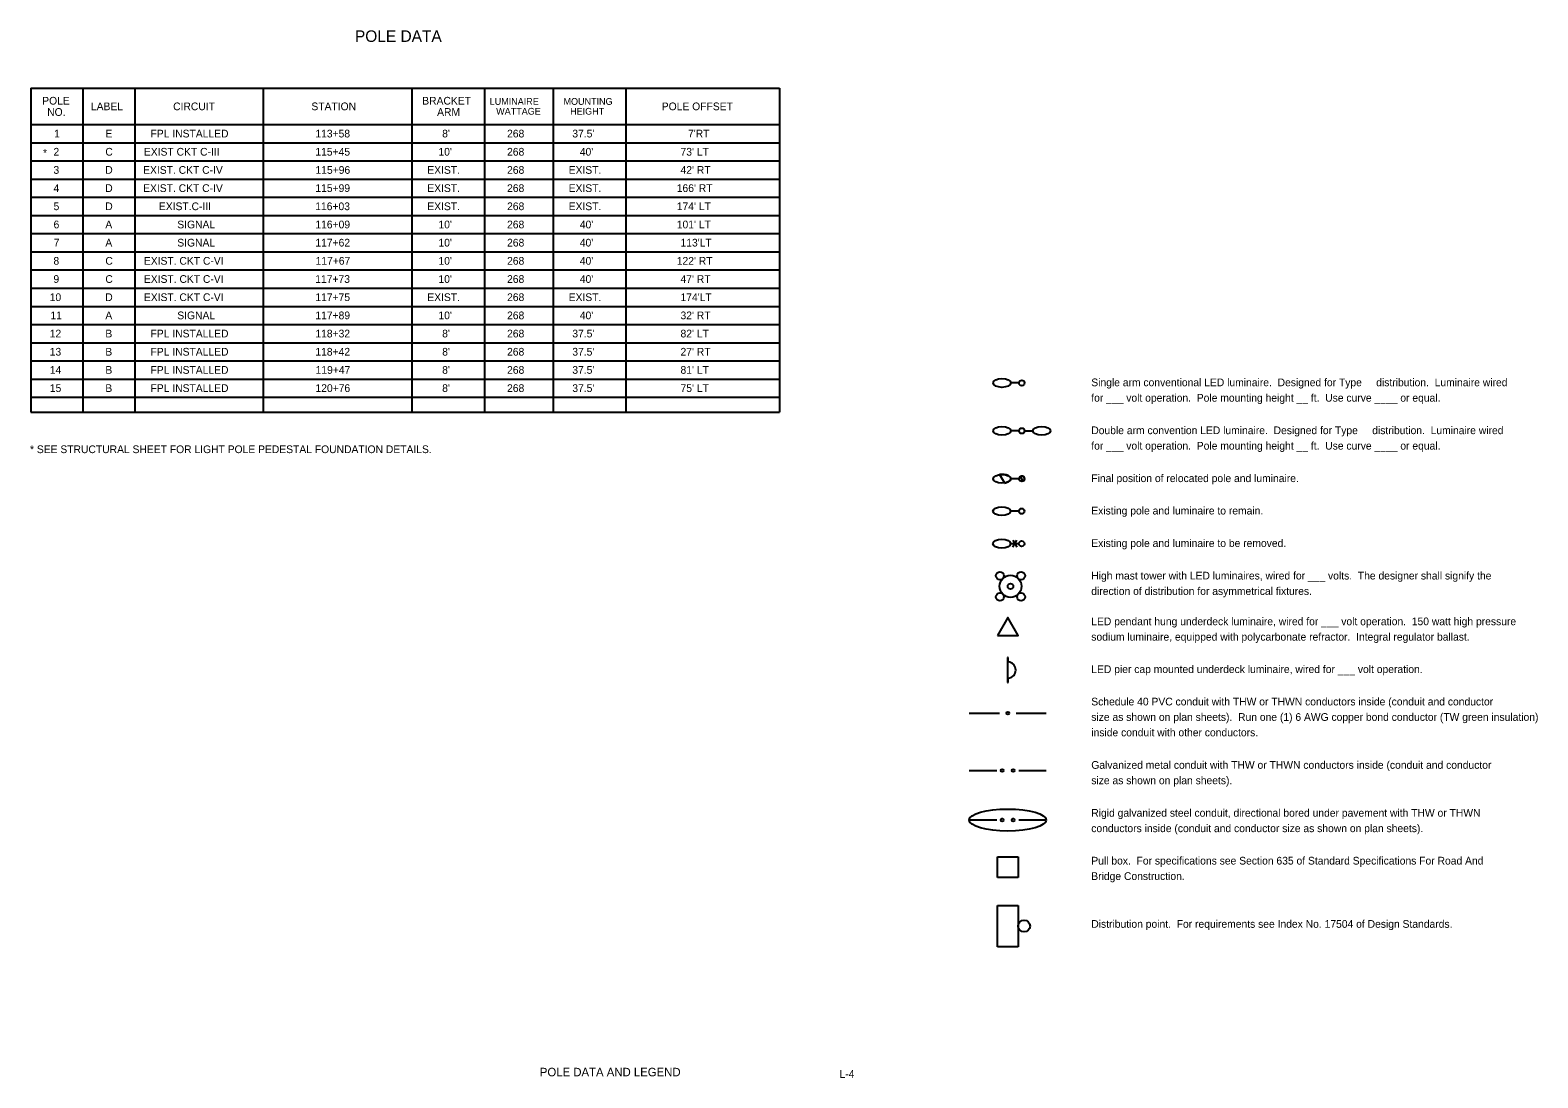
# Model space of a CAD drawing. Extents: x 0.1 to 21.4, y -0.2 to 9.3.
# Drawn here: x 7.72 to 21.4, y -0.21 to 9.3 of the extents above; entities that cross this region are included whole.
import ezdxf

# ---------------------------------------------------------------- set-up
doc = ezdxf.new("R2010")
doc.units = 0
for name, color, linetype in [('NonPlottingEle_dp', 7, 'Continuous'), ('SumBoxBorder_dp', 7, 'Continuous'), ('SumBoxLines_dp', 7, 'Continuous'), ('SumBoxLinesMin_dp', 7, 'Continuous'), ('TextLabel', 7, 'Continuous'), ('TextNotes', 7, 'Continuous')]:
    doc.layers.add(name, color=color, linetype=linetype)

msp = doc.modelspace()

# ---------------------------------------------------------------- linework, layer by layer
at = {"layer": 'SumBoxBorder_dp'}
for p, q in [((7.728, 8.769), (14.523, 8.769)), ((7.728, 8.769), (7.728, 5.829)), ((14.523, 8.769), (14.523, 5.829)), ((7.728, 5.829), (14.523, 5.829))]:
    msp.add_line(p, q, dxfattribs=at)
at = {"layer": 'SumBoxLines_dp'}
for p, q in [((8.2, 8.769), (8.2, 5.829)), ((8.2, 8.769), (8.2, 5.829)), ((8.673, 8.769), (8.673, 5.829)), ((8.673, 8.769), (8.673, 5.829)), ((9.835, 8.769), (9.835, 5.829)), ((9.835, 8.769), (9.835, 5.829)), ((11.185, 8.769), (11.185, 5.829)), ((11.185, 8.769), (11.185, 5.829)), ((11.845, 8.769), (11.845, 5.829)), ((11.845, 8.769), (11.845, 5.829)), ((12.468, 8.769), (12.468, 5.829)), ((12.468, 8.769), (12.468, 5.829)), ((13.128, 8.769), (13.128, 5.829)), ((13.128, 8.769), (13.128, 5.829)), ((7.728, 8.439), (14.523, 8.439)), ((7.728, 8.439), (8.673, 8.439)), ((9.835, 8.439), (14.523, 8.439)), ((16.696, 6.094), (16.621, 6.094)), ((16.696, 5.659), (16.621, 5.659)), ((16.746, 5.659), (16.821, 5.659)), ((16.518, 5.263), (16.563, 5.186)), ((16.696, 5.224), (16.621, 5.224)), ((16.733, 5.203), (16.708, 5.246)), ((16.695, 4.93), (16.62, 4.93)), ((16.639, 4.668), (16.677, 4.603)), ((16.639, 4.603), (16.677, 4.668)), ((16.695, 4.635), (16.62, 4.635)), ((16.599, 3.601), (16.592, 3.601)), ((16.592, 3.601), (16.592, 3.376)), ((16.599, 3.563), (16.599, 3.601)), ((16.592, 3.376), (16.599, 3.376)), ((16.599, 3.376), (16.599, 3.414)), ((16.244, 3.097), (16.518, 3.097)), ((16.669, 3.097), (16.944, 3.097)), ((16.244, 2.576), (16.494, 2.576)), ((16.694, 2.576), (16.944, 2.576)), ((16.244, 2.128), (16.494, 2.128)), ((16.694, 2.128), (16.944, 2.128)), ((16.501, 1.793), (16.688, 1.793)), ((16.501, 1.605), (16.501, 1.793)), ((16.688, 1.793), (16.688, 1.605)), ((16.688, 1.605), (16.501, 1.605)), ((16.501, 1.352), (16.688, 1.352)), ((16.501, 0.977), (16.501, 1.352)), ((16.688, 1.352), (16.688, 0.977)), ((16.688, 0.977), (16.501, 0.977))]:
    msp.add_line(p, q, dxfattribs=at)
msp.add_lwpolyline([(16.502, 3.802), (16.689, 3.802), (16.595, 3.965)], close=True, dxfattribs=at)
for centre, radius in [((16.721, 6.094), 0.025), ((16.721, 5.659), 0.025), ((16.721, 5.224), 0.025), ((16.72, 4.93), 0.025), ((16.72, 4.635), 0.025), ((16.523, 4.344), 0.036), ((16.715, 4.344), 0.036), ((16.619, 4.248), 0.1), ((16.619, 4.248), 0.025), ((16.523, 4.152), 0.036), ((16.715, 4.152), 0.036), ((16.594, 3.097), 0.0125), ((16.544, 2.577), 0.0125), ((16.644, 2.577), 0.0125), ((16.544, 2.127), 0.0125), ((16.644, 2.127), 0.0125), ((16.742, 1.165), 0.054)]:
    msp.add_circle(centre, radius, dxfattribs=at)
for centre, radius, start, end in [((16.721, 5.224), 0.025, 300, 120), ((16.592, 3.488), 0.075, 275.7392, 84.2608)]:
    msp.add_arc(centre, radius, start, end, dxfattribs=at)
for centre, major_axis, ratio in [((16.541, 6.094), (-0.08, 0), 0.5), ((16.541, 5.659), (-0.08, 0), 0.5), ((16.901, 5.659), (0.08, 0), 0.5), ((16.541, 5.224), (0.08, 0), 0.5), ((16.54, 4.93), (-0.08, 0), 0.5), ((16.54, 4.635), (-0.08, 0), 0.5), ((16.594, 2.127), (0.35, 0), 0.285714)]:
    msp.add_ellipse(centre, major_axis=major_axis, ratio=ratio, dxfattribs=at)
msp.add_ellipse((16.541, 5.224), major_axis=(-0.08, 0), ratio=0.5, start_param=1.851831, end_param=4.993424, dxfattribs=at)
at = {"layer": 'SumBoxLinesMin_dp'}
for p, q in [((8.673, 8.439), (9.835, 8.439)), ((7.728, 8.274), (14.523, 8.274)), ((7.728, 8.274), (14.523, 8.274)), ((7.728, 8.109), (14.523, 8.109)), ((7.728, 8.109), (14.523, 8.109)), ((7.728, 7.944), (14.523, 7.944)), ((7.728, 7.944), (14.523, 7.944)), ((7.728, 7.779), (14.523, 7.779)), ((7.728, 7.779), (14.523, 7.779)), ((7.728, 7.614), (14.523, 7.614)), ((7.728, 7.614), (14.523, 7.614)), ((7.728, 7.449), (14.523, 7.449)), ((7.728, 7.449), (14.523, 7.449)), ((7.728, 7.284), (14.523, 7.284)), ((7.728, 7.284), (14.523, 7.284)), ((7.728, 7.119), (14.523, 7.119)), ((7.728, 7.119), (14.523, 7.119)), ((7.728, 6.954), (14.523, 6.954)), ((7.728, 6.954), (14.523, 6.954)), ((7.728, 6.789), (14.523, 6.789)), ((7.728, 6.789), (14.523, 6.789)), ((7.728, 6.624), (14.523, 6.624)), ((7.728, 6.624), (14.523, 6.624)), ((7.728, 6.459), (14.523, 6.459)), ((7.728, 6.459), (14.523, 6.459)), ((7.728, 6.294), (14.523, 6.294)), ((7.728, 6.294), (14.523, 6.294)), ((7.728, 6.129), (14.523, 6.129)), ((7.728, 6.129), (14.523, 6.129)), ((7.728, 5.964), (14.523, 5.964)), ((7.728, 5.964), (14.523, 5.964))]:
    msp.add_line(p, q, dxfattribs=at)

# ---------------------------------------------------------------- texts
at = {"layer": 'NonPlottingEle_dp'}
msp.add_text('L-4', height=0.07, dxfattribs=at).set_placement((15.067, -0.213))
at = {"layer": 'TextLabel'}
for s, height, p in [('POLE DATA', 0.105, (10.669, 9.189)), ('POLE', 0.07, (7.831, 8.62)), ('LABEL', 0.07, (8.273, 8.569)), ('CIRCUIT', 0.07, (9.019, 8.569)), ('STATION', 0.07, (10.274, 8.569)), ('BRACKET', 0.07, (11.28, 8.62)), ('LUMINAIRE', 0.0612, (11.892, 8.618)), ('MOUNTING', 0.0612, (12.562, 8.618)), ('POLE OFFSET', 0.07, (13.454, 8.569)), ('NO.', 0.07, (7.876, 8.518)), ('ARM', 0.07, (11.415, 8.518)), ('WATTAGE', 0.0612, (11.951, 8.529)), ('HEIGHT', 0.0612, (12.622, 8.529)), ('1', 0.07, (7.939, 8.322)), ('E', 0.07, (8.405, 8.322)), ('FPL INSTALLED', 0.07, (8.814, 8.322)), ('113+58', 0.07, (10.31, 8.322)), ("8'", 0.07, (11.461, 8.322)), (' 268', 0.07, (12.024, 8.322)), ("37.5'", 0.07, (12.642, 8.322)), ("7'RT", 0.07, (13.692, 8.322)), ('2', 0.07, (7.933, 8.157)), ('C', 0.07, (8.404, 8.157)), ('EXIST CKT C-III', 0.07, (8.754, 8.157)), ('115+45', 0.07, (10.31, 8.157)), ("10'", 0.07, (11.427, 8.157)), (' 268', 0.07, (12.024, 8.157)), ("40'", 0.07, (12.71, 8.157)), ("73' LT", 0.07, (13.624, 8.157)), ('3', 0.07, (7.933, 7.992)), ('D', 0.07, (8.403, 7.992)), ('EXIST. CKT C-IV', 0.07, (8.747, 7.992)), ('115+96', 0.07, (10.311, 7.992)), ('EXIST.', 0.07, (11.326, 7.992)), (' 268', 0.07, (12.024, 7.992)), ('EXIST.', 0.07, (12.609, 7.992)), ("42' RT", 0.07, (13.624, 7.992)), ('4', 0.07, (7.934, 7.827)), ('D', 0.07, (8.403, 7.827)), ('EXIST. CKT C-IV', 0.07, (8.747, 7.827)), ('115+99', 0.07, (10.31, 7.827)), ('EXIST.', 0.07, (11.326, 7.827)), (' 268', 0.07, (12.024, 7.827)), ('EXIST.', 0.07, (12.609, 7.827)), ("166' RT", 0.07, (13.59, 7.827)), ('5', 0.07, (7.934, 7.662)), ('D', 0.07, (8.403, 7.662)), ('EXIST.C-III', 0.07, (8.89, 7.662)), ('116+03', 0.07, (10.309, 7.662)), ('EXIST.', 0.07, (11.326, 7.662)), (' 268', 0.07, (12.024, 7.662)), ('EXIST.', 0.07, (12.609, 7.662)), ("174' LT", 0.07, (13.59, 7.662)), ('6', 0.07, (7.934, 7.497)), ('A', 0.07, (8.404, 7.497)), ('SIGNAL', 0.07, (9.057, 7.497)), ('116+09', 0.07, (10.31, 7.497)), ("10'", 0.07, (11.427, 7.497)), (' 268', 0.07, (12.024, 7.497)), ("40'", 0.07, (12.71, 7.497)), ("101' LT", 0.07, (13.59, 7.497)), ('7', 0.07, (7.935, 7.332)), ('A', 0.07, (8.404, 7.332)), ('SIGNAL', 0.07, (9.057, 7.332)), ('117+62', 0.07, (10.31, 7.332)), ("10'", 0.07, (11.427, 7.332)), (' 268', 0.07, (12.024, 7.332)), ("40'", 0.07, (12.71, 7.332)), ("113'LT", 0.07, (13.624, 7.332)), ('8', 0.07, (7.933, 7.167)), ('C', 0.07, (8.404, 7.167)), ('EXIST. CKT C-VI', 0.07, (8.754, 7.167)), ('117+67', 0.07, (10.312, 7.167)), ("10'", 0.07, (11.427, 7.167)), (' 268', 0.07, (12.024, 7.167)), ("40'", 0.07, (12.71, 7.167)), ("122' RT", 0.07, (13.59, 7.167)), ('9', 0.07, (7.933, 7.002)), ('C', 0.07, (8.404, 7.002)), ('EXIST. CKT C-VI', 0.07, (8.754, 7.002)), ('117+73', 0.07, (10.309, 7.002)), ("10'", 0.07, (11.427, 7.002)), (' 268', 0.07, (12.024, 7.002)), ("40'", 0.07, (12.71, 7.002)), ("47' RT", 0.07, (13.624, 7.002)), ('10', 0.07, (7.899, 6.837)), ('D', 0.07, (8.403, 6.837)), ('EXIST. CKT C-VI', 0.07, (8.754, 6.837)), ('117+75', 0.07, (10.31, 6.837)), ('EXIST.', 0.07, (11.326, 6.837)), (' 268', 0.07, (12.024, 6.837)), ('EXIST.', 0.07, (12.609, 6.837)), ("174'LT", 0.07, (13.624, 6.837)), ('11', 0.07, (7.906, 6.672)), ('A', 0.07, (8.404, 6.672)), ('SIGNAL', 0.07, (9.057, 6.672)), ('117+89', 0.07, (10.31, 6.672)), ("10'", 0.07, (11.427, 6.672)), (' 268', 0.07, (12.024, 6.672)), ("40'", 0.07, (12.71, 6.672)), ("32' RT", 0.07, (13.624, 6.672)), ('12', 0.07, (7.899, 6.507)), ('B', 0.07, (8.404, 6.507)), ('FPL INSTALLED', 0.07, (8.814, 6.507)), ('118+32', 0.07, (10.31, 6.507)), ("8'", 0.07, (11.461, 6.507)), (' 268', 0.07, (12.024, 6.507)), ("37.5'", 0.07, (12.642, 6.507)), ("82' LT", 0.07, (13.624, 6.507)), ('13', 0.07, (7.899, 6.342)), ('B', 0.07, (8.404, 6.342)), ('FPL INSTALLED', 0.07, (8.814, 6.342)), ('118+42', 0.07, (10.31, 6.342)), ("8'", 0.07, (11.461, 6.342)), (' 268', 0.07, (12.024, 6.342)), ("37.5'", 0.07, (12.642, 6.342)), ("27' RT", 0.07, (13.624, 6.342)), ('14', 0.07, (7.9, 6.177)), ('B', 0.07, (8.404, 6.177)), ('FPL INSTALLED', 0.07, (8.814, 6.177)), ('119+47', 0.07, (10.312, 6.177)), ("8'", 0.07, (11.461, 6.177)), (' 268', 0.07, (12.024, 6.177)), ("37.5'", 0.07, (12.642, 6.177)), ("81' LT", 0.07, (13.624, 6.177)), ('15', 0.07, (7.9, 6.012)), ('B', 0.07, (8.404, 6.012)), ('FPL INSTALLED', 0.07, (8.814, 6.012)), ('120+76', 0.07, (10.311, 6.012)), ("8'", 0.07, (11.461, 6.012)), (' 268', 0.07, (12.024, 6.012)), ("37.5'", 0.07, (12.642, 6.012)), ("75' LT", 0.07, (13.624, 6.012)), ('  POLE DATA AND LEGEND  ', 0.07709, (12.29, -0.199))]:
    msp.add_text(s, height=height, dxfattribs=at).set_placement(p)
at = {"layer": 'TextNotes'}
for s, p in [('*', (7.838, 8.147)), ('Single arm conventional LED luminaire.  Designed for Type     distribution.  Luminaire wired ', (17.352, 6.064)), ('for ___ volt operation.  Pole mounting height __ ft.  Use curve ____ or equal.', (17.352, 5.924)), ('Double arm convention LED luminaire.  Designed for Type     distribution.  Luminaire wired', (17.352, 5.629)), ('* SEE STRUCTURAL SHEET FOR LIGHT POLE PEDESTAL FOUNDATION DETAILS.', (7.72, 5.457)), ('for ___ volt operation.  Pole mounting height __ ft.  Use curve ____ or equal.', (17.352, 5.489)), ('Final position of relocated pole and luminaire.', (17.352, 5.194)), ('Existing pole and luminaire to remain.', (17.352, 4.9)), ('Existing pole and luminaire to be removed.', (17.352, 4.605)), ('High mast tower with LED luminaires, wired for ___ volts.  The designer shall signify the ', (17.352, 4.31)), ('direction of distribution for asymmetrical fixtures.', (17.352, 4.17)), ('LED pendant hung underdeck luminaire, wired for ___ volt operation.  150 watt high pressure', (17.352, 3.895)), ('sodium luminaire, equipped with polycarbonate refractor.  Integral regulator ballast.', (17.352, 3.755)), ('LED pier cap mounted underdeck luminaire, wired for ___ volt operation.', (17.352, 3.461)), ('Schedule 40 PVC conduit with THW or THWN conductors inside (conduit and conductor', (17.352, 3.167)), ('size as shown on plan sheets).  Run one (1) 6 AWG copper bond conductor (TW green insulation)', (17.352, 3.027)), ('inside conduit with other conductors.', (17.352, 2.887)), ('Galvanized metal conduit with THW or THWN conductors inside (conduit and conductor', (17.352, 2.592)), ('size as shown on plan sheets).  ', (17.352, 2.452)), ('Rigid galvanized steel conduit, directional bored under pavement with THW or THWN', (17.352, 2.157)), ('conductors inside (conduit and conductor size as shown on plan sheets). ', (17.352, 2.017)), ('Pull box.  For specifications see Section 635 of Standard Specifications For Road And', (17.352, 1.723)), ('Bridge Construction.', (17.352, 1.583)), ('Distribution point.  For requirements see Index No. 17504 of Design Standards.', (17.352, 1.149))]:
    msp.add_text(s, height=0.07, dxfattribs=at).set_placement(p)

doc.saveas('drawing.dxf')
